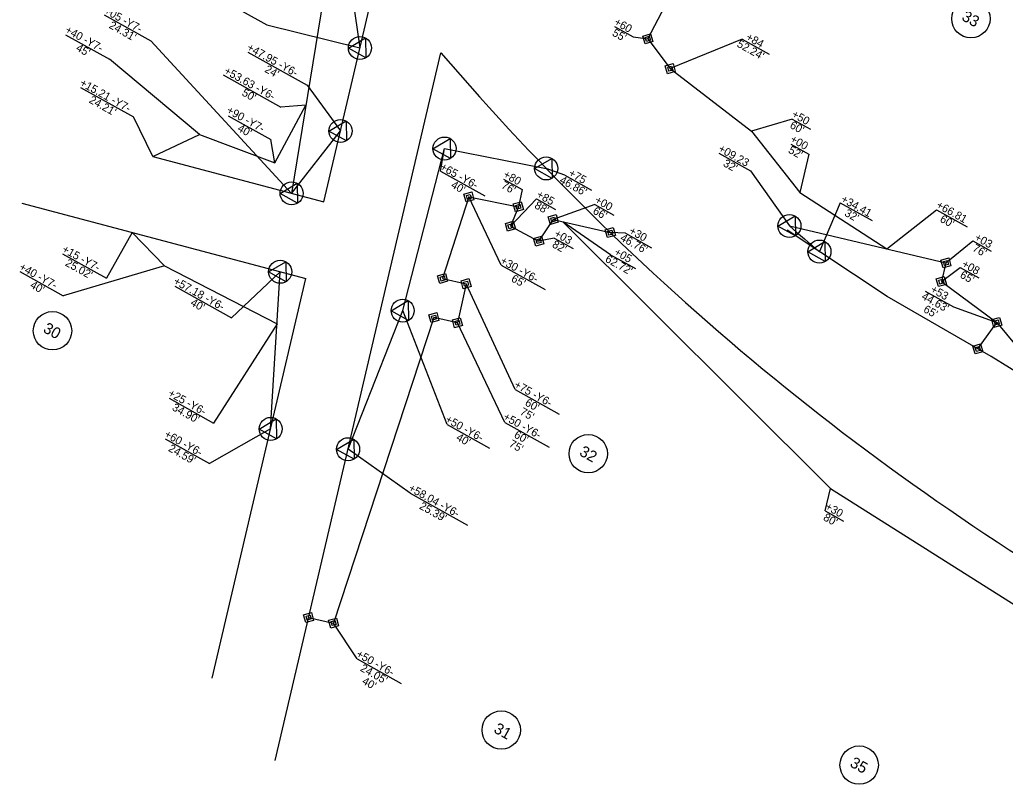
# Model space of a CAD drawing. Extents: x 1762160 to 1765875, y 710174 to 712931.
# Drawn here: x 1763852 to 1764467, y 710824 to 711302 of the extents above; entities that cross this region are included whole.
import ezdxf

# ---------------------------------------------------------------- set-up
doc = ezdxf.new("R2010")
doc.units = 0
for name, color, linetype in [('Exist Building Foundations', 7, 'Continuous'), ('Exist Other Culture Area Outline', 7, 'Continuous'), ('Exist Other Culture Fence Line', 7, 'Continuous'), ('Exist Other Culture Located Object CELL', 7, 'Continuous'), ('Exist Other Culture Sign CELL', 7, 'Continuous'), ('Exist Roads Curbs', 7, 'Continuous'), ('Exist Roads EOP Other', 7, 'Continuous'), ('Exist Roads Soil', 7, 'Continuous'), ('Exist Structure Minor Head and End Wall', 7, 'Continuous'), ('Exist Utilities Other Pole CELL', 7, 'Continuous'), ('Exist Utilities Other Pole With Base CELL', 7, 'Continuous'), ('Exist Vegetation Tree CELL', 7, 'Continuous'), ('Exist Vegetation Woods Line', 7, 'Continuous')]:
    doc.layers.add(name, color=color, linetype=linetype)

msp = doc.modelspace()

# ---------------------------------------------------------------- linework, layer by layer
at = {"layer": 'Exist Building Foundations'}
for p, q in [((1764047.7, 711353.94), (1764021.59, 711193.69)), ((1764244.15, 711290.27), (1764254.99, 711310.89)), ((1764244.15, 711290.27), (1764258.16, 711271.64)), ((1764132.37, 711191.46), (1764115.93, 711140.44)), ((1764132.37, 711191.46), (1764163.26, 711185.29)), ((1764163.26, 711185.29), (1764158.31, 711173.15)), ((1764185.06, 711177.32), (1764175.93, 711163.8)), ((1764185.06, 711177.32), (1764220.72, 711169.13)), ((1764158.31, 711173.15), (1764175.93, 711163.8)), ((1764332.61, 711173.3), (1764430.43, 711150.18)), ((1764430.43, 711150.18), (1764427.54, 711138.54)), ((1764115.93, 711140.44), (1764130.58, 711137.2)), ((1764130.58, 711137.2), (1764125.17, 711112.79)), ((1764427.54, 711138.54), (1764462.19, 711112.99)), ((1764110.53, 711116.03), (1764047.79, 710925.08)), ((1764125.17, 711112.79), (1764110.53, 711116.03)), ((1764032.22, 710928.52), (1764047.79, 710925.08))]:
    msp.add_line(p, q, dxfattribs=at)
at = {"layer": 'Exist Other Culture Area Outline'}
for p, q in [((1764052.51, 711365.95), (1764064.28, 711284.54)), ((1764021.59, 711193.69), (1764052.13, 711232.66)), ((1764091, 711120.35), (1764117.12, 711221.7)), ((1764117.12, 711221.7), (1764180.63, 711209.25)), ((1764008.49, 711046.43), (1764014.44, 711144.65)), ((1764056.87, 711033.72), (1764091, 711120.35))]:
    msp.add_line(p, q, dxfattribs=at)
msp.add_arc((1765296.46, 712280.56), 1468, 228.96094, 229.92288, dxfattribs=at)
at = {"layer": 'Exist Other Culture Fence Line'}
for p, q in [((1764223.24, 711297.97), (1764234.99, 711291.42)), ((1764234.99, 711291.42), (1764244.15, 711290.27)), ((1764303.02, 711290.09), (1764258.16, 711271.64)), ((1764303.02, 711290.09), (1764319.96, 711280.66)), ((1764153.94, 711202.63), (1764165.7, 711196.08)), ((1764165.7, 711196.08), (1764163.26, 711185.29)), ((1764152.44, 711148.83), (1764132.37, 711191.46)), ((1764174.65, 711190.16), (1764158.31, 711173.15)), ((1764174.65, 711190.16), (1764186.41, 711183.62)), ((1764211.12, 711186.67), (1764185.06, 711177.32)), ((1764211.12, 711186.67), (1764222.87, 711180.13)), ((1764185.71, 711165.71), (1764175.93, 711163.8)), ((1764185.71, 711165.71), (1764197.46, 711159.17)), ((1764230.18, 711168.8), (1764246.54, 711159.69)), ((1764430.43, 711150.18), (1764447.21, 711163.95)), ((1764447.21, 711163.95), (1764458.74, 711157.53)), ((1764152.44, 711148.83), (1764179.98, 711133.49)), ((1764427.54, 711138.54), (1764439.38, 711147.28)), ((1764439.38, 711147.28), (1764450.9, 711140.86)), ((1764161.28, 711071.08), (1764130.58, 711137.2)), ((1764154.88, 711050.44), (1764125.17, 711112.79)), ((1764161.28, 711071.08), (1764188.83, 711055.74)), ((1764154.88, 711050.44), (1764182.43, 711035.1)), ((1764062.53, 710902.71), (1764090.07, 710887.37))]:
    msp.add_line(p, q, dxfattribs=at)
for points in [[(1764230.18, 711168.8), (1764220.72, 711169.13)], [(1764062.53, 710902.71), (1764047.79, 710925.08)]]:
    msp.add_lwpolyline(points, dxfattribs=at)
at = {"layer": 'Exist Other Culture Located Object CELL'}
for p, q in [((1763880.25, 711292.8), (1763907.78, 711277.47)), ((1763964.1, 711230.42), (1763907.78, 711277.47)), ((1763978.81, 711267.68), (1764014.87, 711247.6)), ((1763889.72, 711259.81), (1763922.77, 711241.41)), ((1764030.57, 711248.81), (1764014.87, 711247.6)), ((1763934.8, 711216.71), (1763922.77, 711241.41)), ((1763982.02, 711242.08), (1764008.63, 711227.26)), ((1764334.42, 711240.06), (1764308.86, 711232.59)), ((1764334.42, 711240.06), (1764345.8, 711233.73)), ((1764011.13, 711212.71), (1764008.63, 711227.26)), ((1764333.48, 711224.45), (1764344.66, 711218.23)), ((1764344.66, 711218.23), (1764339.04, 711194.26)), ((1764393.38, 711158.94), (1764424.48, 711183.38)), ((1764424.48, 711183.38), (1764443.74, 711172.66)), ((1764220.83, 711155.3), (1764191.06, 711175.94)), ((1763921.92, 711169.19), (1763905.89, 711140.56)), ((1763878.4, 711155.87), (1763905.89, 711140.56)), ((1764220.83, 711155.3), (1764236.35, 711146.66)), ((1763942.22, 711148.28), (1763878.85, 711129.63)), ((1763851.7, 711144.75), (1763878.85, 711129.63)), ((1764012.47, 711112.12), (1763972.8, 711050.1)), ((1763945.04, 711065.56), (1763972.8, 711050.1)), ((1764354.98, 710995.23), (1764358.29, 711009.25)), ((1764354.98, 710995.23), (1764366.51, 710988.81))]:
    msp.add_line(p, q, dxfattribs=at)
at = {"layer": 'Exist Other Culture Sign CELL'}
for p, q in [((1764417.46, 711132.61), (1764435.12, 711122.77)), ((1764435.12, 711122.77), (1764462.19, 711112.99))]:
    msp.add_line(p, q, dxfattribs=at)
at = {"layer": 'Exist Roads Curbs'}
for p, q in [((1764244.15, 711290.27), (1764244.15, 711290.27)), ((1764064.28, 711284.54), (1764064.28, 711284.54)), ((1764258.16, 711271.64), (1764258.16, 711271.64)), ((1764052.13, 711232.66), (1764052.13, 711232.66)), ((1764117.12, 711221.7), (1764117.12, 711221.7)), ((1764180.63, 711209.25), (1764180.63, 711209.25)), ((1764021.59, 711193.69), (1764021.59, 711193.69)), ((1764132.37, 711191.46), (1764132.37, 711191.46)), ((1764163.26, 711185.29), (1764163.26, 711185.29)), ((1764185.06, 711177.32), (1764185.06, 711177.32)), ((1764158.31, 711173.15), (1764158.31, 711173.15)), ((1764332.61, 711173.3), (1764332.61, 711173.3)), ((1764220.72, 711169.13), (1764220.72, 711169.13)), ((1764175.93, 711163.8), (1764175.93, 711163.8)), ((1764351.34, 711157.28), (1764351.34, 711157.28)), ((1764430.43, 711150.18), (1764430.43, 711150.18)), ((1764014.44, 711144.65), (1764014.44, 711144.65)), ((1764115.93, 711140.44), (1764115.93, 711140.44)), ((1764130.58, 711137.2), (1764130.58, 711137.2)), ((1764427.54, 711138.54), (1764427.54, 711138.54)), ((1764091, 711120.35), (1764091, 711120.35)), ((1764110.53, 711116.03), (1764110.53, 711116.03)), ((1764125.17, 711112.79), (1764125.17, 711112.79)), ((1764462.19, 711112.99), (1764462.19, 711112.99)), ((1764450.34, 711096.42), (1764450.34, 711096.42)), ((1764008.49, 711046.43), (1764008.49, 711046.43)), ((1764056.87, 711033.72), (1764056.87, 711033.72)), ((1764032.22, 710928.52), (1764032.22, 710928.52)), ((1764047.79, 710925.08), (1764047.79, 710925.08))]:
    msp.add_line(p, q, dxfattribs=at)
for points in [[(1764057.07, 711284.43), (1764067.79, 711290.83), (1764067.99, 711278.35)], [(1764044.92, 711232.56), (1764055.63, 711238.95), (1764055.84, 711226.48)], [(1764109.91, 711221.6), (1764120.63, 711227.99), (1764120.83, 711215.52)], [(1764173.42, 711209.14), (1764184.13, 711215.54), (1764184.34, 711203.06)], [(1764014.37, 711193.58), (1764025.09, 711199.98), (1764025.29, 711187.5)], [(1764325.4, 711173.2), (1764336.12, 711179.59), (1764336.32, 711167.11)], [(1764344.13, 711157.17), (1764354.84, 711163.57), (1764355.05, 711151.09)], [(1764007.23, 711144.54), (1764017.94, 711150.94), (1764018.15, 711138.46)], [(1764083.79, 711120.25), (1764094.5, 711126.64), (1764094.71, 711114.17)], [(1764001.28, 711046.33), (1764011.99, 711052.72), (1764012.2, 711040.25)], [(1764049.65, 711033.62), (1764060.37, 711040.01), (1764060.58, 711027.54)]]:
    msp.add_lwpolyline(points, close=True, dxfattribs=at)
for centre in [(1764064.28, 711284.54), (1764052.13, 711232.66), (1764117.12, 711221.7), (1764180.63, 711209.25), (1764021.59, 711193.69), (1764332.61, 711173.3), (1764351.34, 711157.28), (1764014.44, 711144.65), (1764091, 711120.35), (1764008.49, 711046.43), (1764056.87, 711033.72)]:
    msp.add_circle(centre, 7.2, dxfattribs=at)
at = {"layer": 'Exist Roads EOP Other'}
for p, q in [((1764258.16, 711271.64), (1764308.86, 711232.59)), ((1764011.13, 711212.71), (1764030.57, 711248.81)), ((1763934.8, 711216.71), (1763964.1, 711230.42)), ((1763964.1, 711230.42), (1764011.13, 711212.71)), ((1764308.86, 711232.59), (1764339.04, 711194.26)), ((1764339.04, 711194.26), (1764393.38, 711158.94)), ((1764191.06, 711175.94), (1764358.29, 711009.25)), ((1763921.92, 711169.19), (1763942.22, 711148.28)), ((1763942.22, 711148.28), (1764012.47, 711112.12)), ((1764358.29, 711009.25), (1764552.62, 710886.29))]:
    msp.add_line(p, q, dxfattribs=at)
at = {"layer": 'Exist Roads Soil'}
for p, q in [((1764450.34, 711096.42), (1764462.19, 711112.99)), ((1764462.19, 711112.99), (1764479.37, 711092.4))]:
    msp.add_line(p, q, dxfattribs=at)
at = {"layer": 'Exist Structure Minor Head and End Wall'}
for points in [[(1764241.01, 711292.02), (1764245.91, 711293.41), (1764247.3, 711288.52), (1764242.4, 711287.12)], [(1764242.58, 711291.14), (1764245.03, 711291.84), (1764245.73, 711289.39), (1764243.28, 711288.7)], [(1764255.01, 711273.39), (1764259.91, 711274.78), (1764261.3, 711269.89), (1764256.4, 711268.49)], [(1764256.58, 711272.51), (1764259.03, 711273.21), (1764259.73, 711270.76), (1764257.28, 711270.07)], [(1764129.22, 711193.22), (1764134.12, 711194.61), (1764135.51, 711189.71), (1764130.62, 711188.32)], [(1764130.8, 711192.34), (1764133.24, 711193.04), (1764133.94, 711190.59), (1764131.49, 711189.89)], [(1764160.11, 711187.04), (1764165.01, 711188.43), (1764166.4, 711183.53), (1764161.51, 711182.14)], [(1764161.68, 711186.16), (1764164.13, 711186.86), (1764164.83, 711184.41), (1764162.38, 711183.71)], [(1764181.91, 711179.07), (1764186.81, 711180.46), (1764188.2, 711175.57), (1764183.31, 711174.17)], [(1764183.49, 711178.19), (1764185.93, 711178.89), (1764186.63, 711176.44), (1764184.18, 711175.75)], [(1764155.17, 711174.9), (1764160.07, 711176.29), (1764161.46, 711171.4), (1764156.56, 711170)], [(1764156.74, 711174.02), (1764159.19, 711174.72), (1764159.89, 711172.27), (1764157.44, 711171.57)], [(1764217.58, 711170.89), (1764222.47, 711172.28), (1764223.87, 711167.38), (1764218.97, 711165.99)], [(1764172.79, 711165.56), (1764177.69, 711166.95), (1764179.08, 711162.05), (1764174.18, 711160.66)], [(1764174.36, 711164.68), (1764176.81, 711165.38), (1764177.51, 711162.93), (1764175.06, 711162.23)], [(1764219.15, 711170.01), (1764221.6, 711170.71), (1764222.29, 711168.26), (1764219.85, 711167.56)], [(1764427.28, 711151.93), (1764432.18, 711153.32), (1764433.57, 711148.42), (1764428.68, 711147.03)], [(1764428.86, 711151.05), (1764431.31, 711151.75), (1764432, 711149.3), (1764429.55, 711148.6)], [(1764112.78, 711142.19), (1764117.68, 711143.59), (1764119.07, 711138.69), (1764114.18, 711137.3)], [(1764114.36, 711141.32), (1764116.81, 711142.02), (1764117.5, 711139.57), (1764115.05, 711138.87)], [(1764127.43, 711138.95), (1764132.33, 711140.35), (1764133.72, 711135.45), (1764128.82, 711134.06)], [(1764424.4, 711140.29), (1764429.29, 711141.69), (1764430.69, 711136.79), (1764425.79, 711135.4)], [(1764129, 711138.08), (1764131.45, 711138.77), (1764132.15, 711136.33), (1764129.7, 711135.63)], [(1764425.97, 711139.42), (1764428.42, 711140.11), (1764429.11, 711137.67), (1764426.67, 711136.97)], [(1764107.38, 711117.78), (1764112.28, 711119.18), (1764113.67, 711114.28), (1764108.78, 711112.89)], [(1764108.96, 711116.91), (1764111.4, 711117.61), (1764112.1, 711115.16), (1764109.65, 711114.46)], [(1764122.03, 711114.54), (1764126.93, 711115.94), (1764128.32, 711111.04), (1764123.42, 711109.65)], [(1764459.04, 711114.74), (1764463.94, 711116.14), (1764465.33, 711111.24), (1764460.44, 711109.85)], [(1764123.6, 711113.67), (1764126.05, 711114.37), (1764126.75, 711111.92), (1764124.3, 711111.22)], [(1764460.62, 711113.87), (1764463.06, 711114.56), (1764463.76, 711112.12), (1764461.31, 711111.42)], [(1764447.2, 711098.17), (1764452.1, 711099.56), (1764453.49, 711094.67), (1764448.59, 711093.27)], [(1764448.77, 711097.29), (1764451.22, 711097.99), (1764451.92, 711095.54), (1764449.47, 711094.84)], [(1764029.07, 710930.27), (1764033.97, 710931.67), (1764035.36, 710926.77), (1764030.47, 710925.38)], [(1764030.64, 710929.4), (1764033.09, 710930.1), (1764033.79, 710927.65), (1764031.34, 710926.95)], [(1764044.65, 710926.83), (1764049.55, 710928.22), (1764050.94, 710923.33), (1764046.04, 710921.93)], [(1764046.22, 710925.95), (1764048.67, 710926.65), (1764049.37, 710924.2), (1764046.92, 710923.5)]]:
    msp.add_lwpolyline(points, close=True, dxfattribs=at)
at = {"layer": 'Exist Utilities Other Pole CELL'}
for p, q in [((1763969.89, 711319.18), (1764006.11, 711299.01)), ((1763904.55, 711305.24), (1763933.66, 711289.03)), ((1763994.24, 711281.95), (1764031.37, 711261.28)), ((1764114.51, 711207.52), (1764117.12, 711221.7)), ((1764288.45, 711218.81), (1764308.38, 711207.71)), ((1764192.23, 711204.99), (1764180.63, 711209.25)), ((1764114.51, 711207.52), (1764142.29, 711192.05)), ((1764192.23, 711204.99), (1764208.93, 711195.69)), ((1764308.38, 711207.71), (1764332.61, 711173.3)), ((1764364.31, 711187.74), (1764384.24, 711176.64)), ((1764014.44, 711144.65), (1763984.13, 711115.91)), ((1763948.54, 711135.73), (1763984.13, 711115.91)), ((1764118.73, 711049.16), (1764091, 711120.35)), ((1764118.73, 711049.16), (1764145.14, 711034.46)), ((1763942.49, 711040.27), (1763970.23, 711024.82)), ((1764095.59, 711006.29), (1764131.46, 710986.31))]:
    msp.add_line(p, q, dxfattribs=at)
for points in [[(1764006.11, 711299.01), (1764064.28, 711284.54)], [(1763933.66, 711289.03), (1764021.59, 711193.69)], [(1764031.37, 711261.28), (1764052.13, 711232.66)], [(1764364.31, 711187.74), (1764351.34, 711157.28)], [(1764008.49, 711046.43), (1763970.23, 711024.82)], [(1764095.59, 711006.29), (1764056.87, 711033.72)]]:
    msp.add_lwpolyline(points, dxfattribs=at)
at = {"layer": 'Exist Utilities Other Pole With Base CELL'}
for p, q in [((1764041.74, 711188.34), (1764073.79, 711325.1)), ((1764011.29, 710839.22), (1764114.92, 711281.46)), ((1763934.8, 711216.71), (1764041.74, 711188.34)), ((1763852.94, 711187.49), (1764030.51, 711140.39)), ((1764393.71, 711129.16), (1764331.16, 711170.67)), ((1763971.99, 710890.67), (1764030.51, 711140.39)), ((1764458.64, 711091.62), (1764393.71, 711129.16)), ((1764524.13, 711051.05), (1764458.64, 711091.62))]:
    msp.add_line(p, q, dxfattribs=at)
msp.add_arc((1765367.59, 712355.39), 1650, 220.60672, 240.8436, dxfattribs=at)
at = {"layer": 'Exist Vegetation Tree CELL'}
for centre in [(1764446, 711302.85), (1763872.19, 711107.76), (1764206.92, 711030.92), (1764152.55, 710858.2), (1764376.2, 710836.28)]:
    msp.add_circle(centre, 12, dxfattribs=at)

# ---------------------------------------------------------------- texts
at = {"layer": 'Exist Other Culture Fence Line'}
for s, rotation, p in [('+60', 330.88857, (1764222.62, 711299.38)), ("55'", 330.88857, (1764221.45, 711292.59)), ("52.24'", 330.88857, (1764299.37, 711285.63)), ('+84', 330.88857, (1764304.97, 711289.95)), ('+80', 330.88857, (1764153.33, 711204.04)), ("76'", 330.88857, (1764152.16, 711197.25)), ('+85', 330.88857, (1764174.12, 711191.53)), ('+00', 330.88857, (1764210.5, 711188.09)), ("88'", 330.88857, (1764172.87, 711184.78)), ("66'", 330.88857, (1764209.34, 711181.3)), ('+30', 330.88857, (1764231.93, 711168.86)), ('+03', 330.88857, (1764185.19, 711167.07)), ("46.76'", 330.88857, (1764226.44, 711164.48)), ('+03', 330.89322, (1764447.81, 711164.7)), ("82'", 330.88857, (1764183.93, 711160.34)), ("76'", 330.89322, (1764446.55, 711157.97)), ('+30 -Y6-', 330.88857, (1764151.49, 711150.2)), ('+08', 330.89322, (1764439.89, 711148.08)), ("65'", 330.88857, (1764158.33, 711138.95)), ("65'", 330.89322, (1764438.72, 711141.3)), ('+75 -Y6-', 330.88857, (1764160.12, 711072.66)), ("60'", 330.88857, (1764166.96, 711061.41)), ('+50 -Y6-', 330.88857, (1764153.28, 711052.62)), ("75'", 330.88857, (1764163.8, 711055.74)), ("60'", 330.88857, (1764160.12, 711041.37)), ("75'", 330.88857, (1764156.96, 711035.69)), ('+50 -Y6-', 330.88857, (1764061.48, 710904.3)), ("24.05'", 330.88857, (1764064.01, 710895.46)), ("40'", 330.88857, (1764065.16, 710887.37))]:
    msp.add_text(s, height=5, rotation=rotation, dxfattribs=at).set_placement(p)
at = {"layer": 'Exist Other Culture Located Object CELL'}
for s, rotation, p in [('+40 -Y7-', 330.88857, (1763879.54, 711294.46)), ("45'", 330.88857, (1763886.38, 711283.21)), ('+53.63 -Y6-', 330.88857, (1763978.88, 711268.84)), ('+15.21 -Y7-', 330.88857, (1763888.77, 711261.33)), ("50'", 330.88857, (1763990.04, 711255.18)), ("24.21'", 330.88857, (1763894.57, 711250.67)), ('+90 -Y7-', 330.88857, (1763980.48, 711244.2)), ('+50', 330.88857, (1764333.59, 711241.69)), ("40'", 330.88857, (1763987.32, 711232.95)), ("60'", 330.88857, (1764332.43, 711234.89)), ('+00', 330.88857, (1764332.64, 711226.13)), ("52'", 330.88857, (1764331.47, 711219.34)), ('+66.81', 330.89322, (1764423.91, 711184.94)), ("60'", 330.89322, (1764426.2, 711176.23)), ('+15 -Y7-', 330.88857, (1763877.68, 711157.31)), ("62.72'", 330.88857, (1764217.06, 711151.22)), ('+05', 330.88857, (1764222.63, 711155.56)), ('+40 -Y7-', 330.88857, (1763850.9, 711146.25)), ("25.02'", 330.88857, (1763879.69, 711148.75)), ("40'", 330.88857, (1763857.74, 711135)), ('+25 -Y6-', 330.88857, (1763943.94, 711067.32)), ("34.90'", 330.88857, (1763946.46, 711058.48)), ('+30', 330.88857, (1764354.5, 710996.48)), ("80'", 330.88857, (1764353.33, 710989.69))]:
    msp.add_text(s, height=5, rotation=rotation, dxfattribs=at).set_placement(p)
at = {"layer": 'Exist Other Culture Sign CELL'}
for s, p in [('+53 ', (1764420.31, 711132.23)), ("44.63'", (1764414.73, 711127.89)), ("65'", (1764415.89, 711119.81))]:
    msp.add_text(s, height=5, rotation=330.89322, dxfattribs=at).set_placement(p)
at = {"layer": 'Exist Utilities Other Pole CELL'}
for s, p in [('+05 -Y7-', (1763904.01, 711306.48)), ("24.31'", (1763907.05, 711297.34)), ('+47.95 -Y6-', (1763993.16, 711283.49)), ("24'", (1764004.32, 711269.84)), ('+09.23', (1764287.7, 711220.16)), ("32'", (1764290.76, 711211.01)), ('+65 -Y6-', (1764113.87, 711208.81)), ("46.86'", (1764188.55, 711200.57)), ('+75', (1764194.13, 711204.91)), ("40'", (1764120.71, 711197.56)), ('+34.41', (1764364.33, 711188.66)), ("32'", (1764366.62, 711179.95)), ('+57.18 -Y6-', (1763947.29, 711137.36)), ("40'", (1763957.93, 711123.99)), ('+50 -Y6-', (1764117.12, 711050.99)), ('+60 -Y6-', (1763941.6, 711041.7)), ("40'", (1764123.97, 711039.74)), ("24.59'", (1763944.13, 711032.85)), ('+58.04 -Y6-', (1764094.1, 711008.05)), ("25.39'", (1764100.94, 710996.8))]:
    msp.add_text(s, height=5, rotation=330.88857, dxfattribs=at).set_placement(p)
at = {"layer": 'Exist Vegetation Woods Line'}
for s, p in [('33', (1764439.71, 711302.32)), ('30', (1763865.77, 711107.3)), ('32', (1764200.83, 711030.27)), ('31', (1764147.33, 710857.07)), ('35', (1764369.89, 710835.75))]:
    msp.add_text(s, height=7, rotation=330.88857, dxfattribs=at).set_placement(p)

doc.saveas('drawing.dxf')
